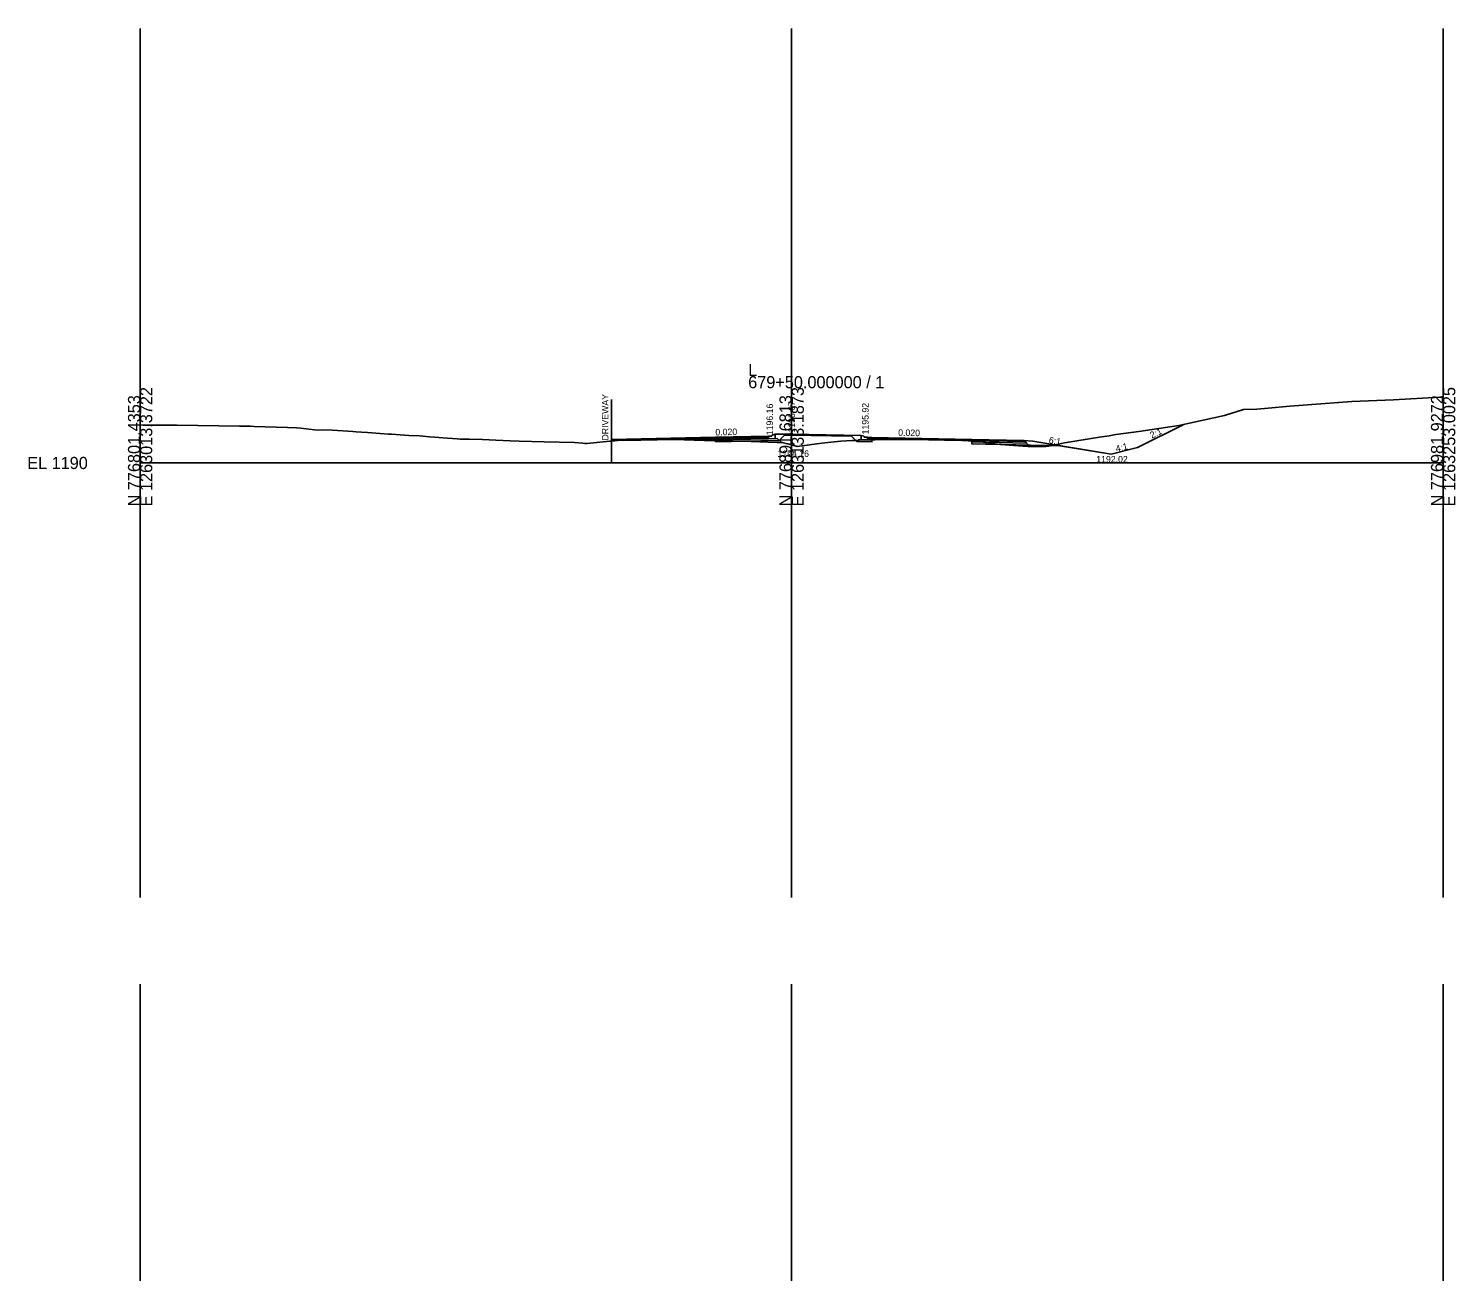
# Model space of a CAD drawing. Extents: x -41 to 1262860, y -100 to 777489.
# Drawn here: x 474.3 to 802.8, y 2878.9 to 3165 of the extents above; entities that cross this region are included whole.
import ezdxf

# ---------------------------------------------------------------- set-up
doc = ezdxf.new("R2010")
doc.units = 0
for name, color, linetype in [('Exist Cross Section Cell', 7, 'Continuous'), ('Exist XS Center Line Elevation Label', 7, 'Continuous'), ('Exist XS Ground Line', 7, 'Continuous'), ('Prop CMT Pvmt Course 1', 7, 'Continuous'), ('Prop CMT Pvmt Surface', 7, 'Continuous'), ('Prop CMT Shear Line', 7, 'Continuous'), ('Prop CMT Shld Paved Course 1', 7, 'Continuous'), ('Prop CMT Shld Paved Course 2', 7, 'Continuous'), ('Prop CMT Shld Paved Course 4', 7, 'Continuous'), ('Prop CMT Subgrade Earthwork', 7, 'Continuous'), ('Prop Conc Curb and Gutter', 7, 'Continuous'), ('Prop Conc Island Cover', 7, 'Continuous'), ('Prop XS Ditch Standard Text', 7, 'Continuous'), ('Prop XS Earthwork Shape', 7, 'Continuous'), ('Prop XS Elevation Labels', 7, 'Continuous'), ('Prop XS Exc Vertical Line 1', 7, 'Continuous'), ('Prop XS Exc Vertical Line 2', 7, 'Continuous'), ('Prop XS Exc Vertical Line 3', 7, 'Continuous'), ('Prop XS Finish Grade', 7, 'Continuous'), ('Prop XS Hydro Elevations', 7, 'Continuous'), ('Prop XS SE Text', 7, 'Continuous'), ('Prop XS Side Slope Text', 7, 'Continuous'), ('Scratch_Level_4', 7, 'Continuous'), ('Scratch_Level_6', 7, 'Continuous')]:
    doc.layers.add(name, color=color, linetype=linetype)

msp = doc.modelspace()

# ---------------------------------------------------------------- linework, layer by layer
at = {"layer": 'Exist Cross Section Cell'}
for p, q in [((650, 3065), (650, 3085)), ((500, 3065), (650, 3065)), ((650, 3065), (800, 3065))]:
    msp.add_line(p, q, dxfattribs=at)
at = {"layer": 'Exist XS Ground Line'}
msp.add_lwpolyline([(500, 3073.76), (500.72, 3073.74), (508.53, 3073.7), (522.87, 3073.5), (525.42, 3073.49), (526.28, 3073.42), (533.92, 3073.14), (535.99, 3073.12), (537.02, 3073.03), (540.78, 3072.57), (542.03, 3072.6), (544.29, 3072.57), (548.97, 3072.21), (549.71, 3072.16), (550.95, 3072.09), (552.32, 3072.01), (555.28, 3071.8), (557.22, 3071.66), (557.85, 3071.62), (561.85, 3071.36), (564.29, 3071.21), (566.59, 3071.02), (567.89, 3070.94), (569.67, 3070.79), (573.03, 3070.54), (573.65, 3070.5), (574.94, 3070.47), (575.79, 3070.45), (578.8, 3070.41), (581.92, 3070.25), (585.2, 3070.08), (587.28, 3069.99), (593.02, 3069.84), (599.98, 3069.74), (601.96, 3069.55), (602.36, 3069.51), (602.68, 3069.49), (602.86, 3069.5), (608.13, 3070), (608.52, 3070.03), (610.72, 3070.22), (615.27, 3070.28), (622.85, 3070.39), (629.92, 3070.21), (635.44, 3070.08), (640.7, 3069.93), (644.63, 3069.8), (646.64, 3069.74), (647.81, 3069.71), (648.74, 3069.46), (649.11, 3069.38), (649.96, 3069.17), (651.28, 3068.8), (654.12, 3069.19), (656.93, 3069.56), (659.05, 3069.78), (661.33, 3070.03), (663.94, 3070.16), (665.57, 3070.25), (672.97, 3070.37), (677.77, 3070.44), (685.2, 3070.26), (689.24, 3070.17), (690.62, 3070.08), (693.01, 3069.93), (697.36, 3069.33), (698.22, 3069.23), (700.07, 3069.08), (704.37, 3068.8), (708.53, 3068.78), (709.13, 3068.85), (710.78, 3069.19), (712.83, 3069.65), (720.87, 3070.93), (723.09, 3071.28), (724.67, 3071.52), (729.93, 3072.25), (739.16, 3073.62), (749.68, 3075.96), (749.93, 3076.01), (753.8, 3077.23), (754, 3077.29), (754.13, 3077.29), (757.11, 3077.42), (759.72, 3077.65), (764.67, 3078.06), (779, 3079.14), (788.55, 3079.57), (799.27, 3080.12), (800, 3080.14)], dxfattribs=at)
at = {"layer": 'Prop CMT Pvmt Course 1'}
for p, q in [((632.5, 3070.66), (644.68, 3070.9)), ((644.68, 3070.9), (644.68, 3071.15)), ((667.5, 3070.91), (667.5, 3070.66)), ((668.5, 3070.64), (667.5, 3070.66))]:
    msp.add_line(p, q, dxfattribs=at)
for points in [[(608.5, 3070.43), (608.5, 3070.18), (632.5, 3070.66), (632.5, 3070.66), (632.5, 3070.91), (632.5, 3070.91), (632.5, 3070.91), (608.5, 3070.43), (608.5, 3070.43)], [(691.5, 3070.43), (691.5, 3070.18), (668.5, 3070.64), (668.5, 3070.64), (668.5, 3070.64), (668.5, 3070.89), (668.5, 3070.89), (668.5, 3070.89), (668.5, 3070.89), (691.5, 3070.43), (691.5, 3070.43)]]:
    msp.add_lwpolyline(points, dxfattribs=at)
at = {"layer": 'Prop CMT Pvmt Surface'}
for p, q in [((608.5, 3070.43), (632.5, 3070.91)), ((632.5, 3070.91), (644.68, 3071.15)), ((668.5, 3070.89), (667.5, 3070.91)), ((668.5, 3070.89), (691.5, 3070.43)), ((691.5, 3070.43), (703.5, 3070.19))]:
    msp.add_line(p, q, dxfattribs=at)
at = {"layer": 'Prop CMT Shear Line'}
msp.add_line((608.5, 3079.58), (608.5, 3065.14), dxfattribs=at)
at = {"layer": 'Prop CMT Shld Paved Course 1'}
for p, q in [((691.5, 3070.43), (691.5, 3070.43)), ((691.5, 3070.43), (691.5, 3070.43)), ((691.5, 3070.43), (691.5, 3070.18)), ((691.5, 3070.18), (691.5, 3070.18)), ((691.5, 3070.18), (703.76, 3069.93)), ((695.5, 3070.35), (695.5, 3070.35)), ((703.76, 3069.93), (703.5, 3070.19))]:
    msp.add_line(p, q, dxfattribs=at)
at = {"layer": 'Prop CMT Shld Paved Course 2'}
for p, q in [((608.52, 3070.18), (608.5, 3070.18)), ((608.5, 3070.18), (608.5, 3070.18)), ((608.5, 3070.18), (608.5, 3070.03)), ((608.5, 3070.03), (608.52, 3070.03)), ((610.72, 3070.22), (608.52, 3070.18)), ((608.52, 3070.03), (610.72, 3070.22)), ((608.52, 3070.18), (608.52, 3070.18)), ((608.52, 3070.03), (608.52, 3070.03)), ((615.27, 3070.31), (610.72, 3070.22)), ((610.72, 3070.22), (615.27, 3070.28)), ((610.72, 3070.22), (610.72, 3070.22)), ((610.72, 3070.22), (610.72, 3070.22)), ((610.72, 3070.22), (610.72, 3070.22)), ((610.72, 3070.22), (610.72, 3070.22)), ((610.72, 3070.22), (610.72, 3070.22)), ((610.72, 3070.22), (610.72, 3070.22)), ((610.72, 3070.22), (610.72, 3070.22)), ((610.72, 3070.22), (610.72, 3070.22)), ((610.72, 3070.22), (610.72, 3070.22)), ((610.72, 3070.22), (610.72, 3070.22)), ((622.85, 3070.46), (615.27, 3070.31)), ((615.27, 3070.28), (622.85, 3070.39)), ((615.27, 3070.31), (615.27, 3070.31)), ((615.27, 3070.28), (615.27, 3070.28)), ((629.92, 3070.6), (622.85, 3070.46)), ((622.85, 3070.39), (628.64, 3070.25)), ((628.64, 3070.25), (629.92, 3070.27)), ((628.64, 3070.25), (628.64, 3070.25)), ((632.5, 3070.66), (629.92, 3070.6)), ((629.92, 3070.6), (629.92, 3070.6)), ((629.92, 3070.27), (632.5, 3070.32)), ((629.92, 3070.27), (629.92, 3070.27)), ((632.5, 3070.32), (632.5, 3070.66)), ((632.5, 3070.66), (632.5, 3070.66)), ((632.5, 3070.32), (644.68, 3070.57)), ((644.68, 3070.9), (644.68, 3070.57)), ((644.68, 3070.57), (644.68, 3070.57)), ((667.5, 3070.32), (667.5, 3070.66)), ((668.5, 3070.3), (667.5, 3070.32)), ((668.5, 3070.3), (668.5, 3070.64)), ((668.5, 3070.64), (668.5, 3070.64)), ((668.5, 3070.64), (668.5, 3070.64)), ((668.5, 3070.64), (668.5, 3070.64)), ((668.5, 3070.64), (672.97, 3070.55)), ((668.64, 3070.3), (668.5, 3070.3)), ((668.5, 3070.3), (668.5, 3070.3)), ((672.97, 3070.37), (668.64, 3070.3)), ((668.64, 3070.3), (668.64, 3070.3)), ((668.64, 3070.3), (668.64, 3070.3)), ((672.97, 3070.55), (672.97, 3070.55)), ((672.97, 3070.55), (677.77, 3070.45)), ((677.77, 3070.44), (672.97, 3070.37)), ((672.97, 3070.37), (672.97, 3070.37)), ((677.77, 3070.45), (677.77, 3070.45)), ((677.77, 3070.45), (677.77, 3070.45)), ((677.77, 3070.45), (677.77, 3070.45)), ((677.77, 3070.45), (685.2, 3070.3)), ((685.2, 3070.26), (677.77, 3070.44)), ((677.77, 3070.44), (677.77, 3070.44)), ((677.77, 3070.44), (677.77, 3070.44)), ((677.77, 3070.44), (677.77, 3070.44)), ((685.2, 3070.3), (685.2, 3070.3)), ((685.2, 3070.3), (689.24, 3070.22)), ((689.24, 3070.17), (685.2, 3070.26)), ((685.2, 3070.26), (685.2, 3070.26)), ((689.24, 3070.22), (689.24, 3070.22)), ((689.24, 3070.22), (689.24, 3070.22)), ((689.24, 3070.22), (689.24, 3070.22)), ((689.24, 3070.22), (689.24, 3070.22)), ((689.24, 3070.22), (690.62, 3070.19)), ((690.62, 3070.08), (689.24, 3070.17)), ((689.24, 3070.17), (689.24, 3070.17)), ((689.24, 3070.17), (689.24, 3070.17)), ((689.24, 3070.17), (689.24, 3070.17)), ((689.24, 3070.17), (689.24, 3070.17)), ((690.62, 3070.19), (691.5, 3070.18)), ((690.62, 3070.19), (690.62, 3070.19)), ((691.5, 3070.03), (690.62, 3070.08)), ((690.62, 3070.08), (690.62, 3070.08)), ((691.5, 3070.18), (691.5, 3070.18)), ((691.5, 3070.18), (691.5, 3070.18)), ((691.5, 3070.18), (691.5, 3069.84)), ((691.5, 3070.18), (691.5, 3070.18)), ((691.5, 3070.18), (691.5, 3070.18)), ((691.5, 3070.18), (691.5, 3070.03)), ((691.5, 3070.03), (691.5, 3070.03)), ((691.5, 3069.84), (691.5, 3069.84)), ((691.5, 3069.84), (704.1, 3069.59)), ((704.1, 3069.59), (703.76, 3069.93))]:
    msp.add_line(p, q, dxfattribs=at)
at = {"layer": 'Prop CMT Shld Paved Course 4'}
for p, q in [((629.92, 3070.21), (628.64, 3070.25)), ((629.92, 3070.21), (632.5, 3070.15)), ((632.5, 3070.32), (632.5, 3069.86)), ((632.5, 3069.86), (647.13, 3070.16)), ((644.68, 3070.57), (646.68, 3070.61)), ((646.68, 3070.61), (647.13, 3070.16)), ((665.5, 3070.36), (665.05, 3069.91)), ((668.5, 3069.84), (665.05, 3069.91)), ((667.5, 3070.32), (665.5, 3070.36)), ((668.5, 3069.84), (668.5, 3070.3)), ((668.64, 3070.3), (668.5, 3070.3)), ((691.5, 3069.84), (691.5, 3069.84)), ((691.5, 3069.84), (691.5, 3069.84)), ((691.5, 3069.84), (691.5, 3069.38)), ((691.5, 3069.38), (704.56, 3069.12)), ((704.56, 3069.12), (704.1, 3069.59))]:
    msp.add_line(p, q, dxfattribs=at)
at = {"layer": 'Prop CMT Subgrade Earthwork'}
for p, q in [((647.13, 3070.16), (632.5, 3069.86)), ((632.5, 3069.86), (632.5, 3070.15)), ((647.13, 3070.16), (648.62, 3071.65)), ((665.05, 3069.91), (663.56, 3071.4)), ((665.05, 3069.91), (668.5, 3069.84)), ((668.5, 3069.84), (668.5, 3070.3)), ((691.5, 3070.03), (691.5, 3069.38)), ((691.5, 3069.38), (711.78, 3068.98))]:
    msp.add_line(p, q, dxfattribs=at)
at = {"layer": 'Prop Conc Curb and Gutter'}
for p, q in [((645.37, 3071.16), (644.68, 3071.15)), ((644.68, 3071.15), (644.68, 3070.57)), ((644.68, 3070.57), (646.18, 3070.6)), ((645.43, 3071.24), (645.43, 3071.23)), ((646.18, 3071.6), (645.53, 3071.38)), ((646.18, 3070.6), (646.18, 3071.6)), ((646.18, 3070.6), (646.18, 3070.6)), ((666, 3071.35), (666.65, 3071.14)), ((666, 3070.35), (666, 3071.35)), ((667.5, 3070.32), (666, 3070.35)), ((666.75, 3071), (666.75, 3070.98)), ((666.81, 3070.92), (667.5, 3070.91)), ((667.5, 3070.32), (667.5, 3070.91))]:
    msp.add_line(p, q, dxfattribs=at)
for centre, radius, start, end in [((645.37, 3071.23), 0.0625, 271.1458, 360), ((645.58, 3071.24), 0.146, 108.435, 180), ((666.6, 3071), 0.146, 0, 71.565), ((666.81, 3070.98), 0.0625, 180, 268.8542)]:
    msp.add_arc(centre, radius, start, end, dxfattribs=at)
at = {"layer": 'Prop Conc Island Cover'}
for p, q in [((646.18, 3071.6), (650, 3071.67)), ((646.18, 3071.33), (646.18, 3071.33)), ((666, 3071.35), (650, 3071.67))]:
    msp.add_line(p, q, dxfattribs=at)
at = {"layer": 'Prop XS Earthwork Shape'}
for points in [[(739.16, 3073.62), (740.28, 3073.86), (729.6, 3068.53), (723.56, 3067.02), (711.78, 3068.98), (710.66, 3069.17), (710.78, 3069.19), (712.83, 3069.65), (720.87, 3070.93), (723.09, 3071.28), (724.67, 3071.52), (729.93, 3072.25)], [(632.5, 3069.86), (632.5, 3070.15), (635.44, 3070.08), (638.63, 3069.99)], [(663.94, 3070.16), (664.76, 3070.21), (663.82, 3071.15), (650, 3071.42), (648.36, 3071.39), (647.13, 3070.16), (638.63, 3069.99), (640.7, 3069.93), (644.63, 3069.8), (646.64, 3069.74), (647.81, 3069.71), (648.74, 3069.46), (649.11, 3069.38), (649.96, 3069.17), (651.28, 3068.8), (654.12, 3069.19), (656.93, 3069.56), (659.05, 3069.78), (661.33, 3070.03)], [(665.05, 3069.91), (664.76, 3070.21), (665.57, 3070.25), (668.5, 3070.3), (668.5, 3069.84)], [(697.36, 3069.33), (697.97, 3069.26), (691.5, 3069.38), (691.5, 3070.03), (693.01, 3069.93)], [(708.53, 3068.78), (709.13, 3068.85), (709.93, 3069.02), (704.56, 3069.12), (697.97, 3069.26), (698.22, 3069.23), (700.07, 3069.08), (704.37, 3068.8)], [(709.93, 3069.02), (710.66, 3069.17), (711.78, 3068.98)]]:
    msp.add_lwpolyline(points, close=True, dxfattribs=at)
at = {"layer": 'Prop XS Exc Vertical Line 1'}
for p, q in [((500, 2965), (500, 3165)), ((500, 2745), (500, 2945))]:
    msp.add_line(p, q, dxfattribs=at)
at = {"layer": 'Prop XS Exc Vertical Line 2'}
for p, q in [((650, 2965), (650, 3165)), ((650, 2745), (650, 2945))]:
    msp.add_line(p, q, dxfattribs=at)
at = {"layer": 'Prop XS Exc Vertical Line 3'}
for p, q in [((800, 2965), (800, 3165)), ((800, 2745), (800, 2945))]:
    msp.add_line(p, q, dxfattribs=at)
at = {"layer": 'Prop XS Finish Grade'}
for p, q in [((729.6, 3068.53), (740.28, 3073.86)), ((703.5, 3070.19), (705.5, 3070.03)), ((703.5, 3070.19), (704.56, 3069.12)), ((705.5, 3070.03), (723.56, 3067.02)), ((723.56, 3067.02), (729.6, 3068.53))]:
    msp.add_line(p, q, dxfattribs=at)
at = {"layer": 'Scratch_Level_4'}
for p, q in [((800, 2965), (800, 3165)), ((800, 2745), (800, 2945))]:
    msp.add_line(p, q, dxfattribs=at)
at = {"layer": 'Scratch_Level_6'}
for p, q in [((500, 2965), (500, 3165)), ((500, 2745), (500, 2945))]:
    msp.add_line(p, q, dxfattribs=at)

# ---------------------------------------------------------------- texts
at = {"layer": 'Exist Cross Section Cell'}
for s, p in [('679+50.000000 / 1', (640, 3082.2)), ('L', (640, 3085)), ('EL 1190', (474, 3063.6))]:
    msp.add_text(s, height=2.8, dxfattribs=at).set_placement(p)
for s, p in [('E 1263013.3722', (502.8, 3055)), ('E 1263133.1873', (652.8, 3055)), ('E 1263253.0025', (802.8, 3055)), ('N 776801.4353', (500, 3055)), ('N 776891.6813', (650, 3055)), ('N 776981.9272', (800, 3055))]:
    msp.add_text(s, height=2.8, rotation=90, dxfattribs=at).set_placement(p)
at = {"layer": 'Exist XS Center Line Elevation Label'}
msp.add_text('1194.16', height=1.5, dxfattribs=at).set_placement((646.74, 3066.41))
at = {"layer": 'Prop XS Ditch Standard Text'}
msp.add_text('1192.02', height=1.5, dxfattribs=at).set_placement((720.14, 3065.11))
at = {"layer": 'Prop XS Elevation Labels'}
for s, p in [('1196.16', (645.71, 3071.4)), ('1195.92', (667.72, 3071.58))]:
    msp.add_text(s, height=1.5, rotation=90, dxfattribs=at).set_placement(p)
at = {"layer": 'Prop XS Hydro Elevations'}
for s, p in [('DRIVEWAY', (607.82, 3070.17)), ('1196.67', (650.75, 3071.99))]:
    msp.add_text(s, height=1.5, rotation=90, dxfattribs=at).set_placement(p)
at = {"layer": 'Prop XS SE Text'}
for rotation, p in [(1.1458, (632.46, 3071.34)), (358.8542, (674.52, 3071.26))]:
    msp.add_text('0.020', height=1.5, rotation=rotation, dxfattribs=at).set_placement(p)
at = {"layer": 'Prop XS Side Slope Text'}
for s, rotation, p in [('2:1', 24.7387, (732.92, 3070.61)), ('6:1', 350.5377, (709.13, 3069.57)), ('4:1', 14.0362, (724.81, 3067.51))]:
    msp.add_text(s, height=1.5, rotation=rotation, dxfattribs=at).set_placement(p)

doc.saveas('drawing.dxf')
